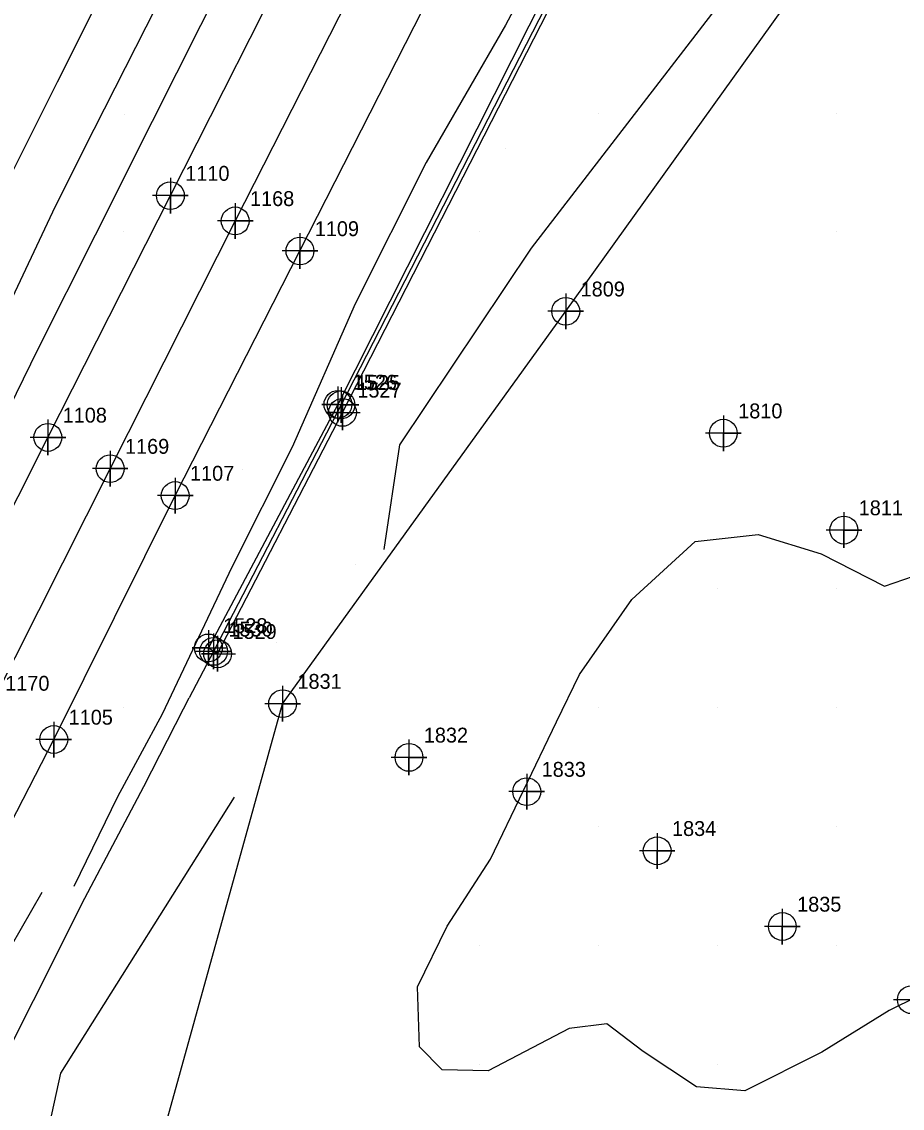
# Model space of a CAD drawing. Extents: x 2062781 to 2066835, y 358981 to 366501.
# Drawn here: x 2063838 to 2063986.2, y 360927.9 to 361110.7 of the extents above; entities that cross this region are included whole.
import ezdxf

# ---------------------------------------------------------------- set-up
doc = ezdxf.new("R2010")
doc.units = 0
for name, color, linetype in [('Exist DTM Breakline', 7, 'Continuous'), ('Exist DTM Breakline Cogo Number', 7, 'Continuous'), ('Exist DTM Breakline Cogo Point CELL', 7, 'Continuous'), ('Exist DTM Crownline', 7, 'Continuous'), ('Exist DTM Crownline Cogo Number', 7, 'Continuous'), ('Exist DTM Crownline Cogo Point CELL', 7, 'Continuous'), ('Exist DTM Regular Point CELL', 7, 'Continuous'), ('Exist DTM Regular Point Cogo Number', 7, 'Continuous'), ('Exist DTM Ridgeline', 7, 'Continuous'), ('Exist DTM Ridgeline Cogo Number', 7, 'Continuous'), ('Exist DTM Ridgeline Cogo Point CELL', 7, 'Continuous'), ('Exist Roads Curbs', 7, 'Continuous'), ('Exist Roads Curbs Cogo Number', 7, 'Continuous'), ('Exist Roads Curbs Cogo Point CELL', 7, 'Continuous'), ('Exist Roads EOP', 7, 'Continuous'), ('Exist Roads EOP Cogo Number', 7, 'Continuous'), ('Exist Roads EOP Cogo Point CELL', 7, 'Continuous'), ('PH Exist DTM Breakline', 7, 'Continuous'), ('PH Exist DTM Point', 7, 'Continuous')]:
    doc.layers.add(name, color=color, linetype=linetype)

msp = doc.modelspace()

# ---------------------------------------------------------------- linework, layer by layer
at = {"layer": 'Exist DTM Breakline'}
msp.add_line((2063870.34, 361004.8), (2063866.24, 360996.99), dxfattribs=at)
msp.add_lwpolyline([(2064057.56, 361350.08), (2064041.78, 361331.46), (2064030.47, 361314.75), (2064022.01, 361300.66), (2063997.63, 361253.31), (2063965.85, 361191.78), (2063927.22, 361115.25), (2063891.78, 361046.28), (2063870.34, 361004.8)], dxfattribs=at)
at = {"layer": 'Exist DTM Breakline Cogo Point CELL'}
for points in [[(2063891.78, 361049.28), (2063891.78, 361043.28), (2063891.78, 361046.28), (2063894.78, 361046.28), (2063888.78, 361046.28)], [(2063891.78, 361049.28), (2063891.78, 361043.28), (2063891.78, 361046.28), (2063894.78, 361046.28), (2063888.78, 361046.28)], [(2063891.78, 361049.28), (2063891.78, 361043.28), (2063891.78, 361046.28), (2063894.78, 361046.28), (2063888.78, 361046.28)], [(2063870.34, 361007.8), (2063870.34, 361001.8), (2063870.34, 361004.8), (2063873.34, 361004.8), (2063867.34, 361004.8)], [(2063870.34, 361007.8), (2063870.34, 361001.8), (2063870.34, 361004.8), (2063873.34, 361004.8), (2063867.34, 361004.8)], [(2063870.34, 361007.8), (2063870.34, 361001.8), (2063870.34, 361004.8), (2063873.34, 361004.8), (2063867.34, 361004.8)]]:
    msp.add_lwpolyline(points, dxfattribs=at)
for centre in [(2063891.78, 361046.28), (2063891.78, 361046.28), (2063891.78, 361046.28), (2063870.34, 361004.8), (2063870.34, 361004.8), (2063870.34, 361004.8)]:
    msp.add_circle(centre, 2.34, dxfattribs=at)
at = {"layer": 'Exist DTM Crownline'}
msp.add_lwpolyline([(2064265.44, 361845.69), (2064239.97, 361795.64), (2064213.32, 361743.86), (2064188.56, 361695.08), (2064163.47, 361645.6), (2064134.87, 361589.21), (2064123.65, 361567.03), (2064102.77, 361525.75), (2064081.5, 361483.76), (2064060.49, 361443.22), (2064039.79, 361402.12), (2064017.95, 361359.29), (2063998.02, 361320.11), (2063977.86, 361280.75), (2063957.66, 361241.43), (2063938.49, 361203.85), (2063917.61, 361163.02), (2063896.2, 361120.91), (2063873.97, 361077.23), (2063852.93, 361035.55), (2063832.77, 360995.69), (2063813.38, 360956.99), (2063791.84, 360915.2), (2063771.3, 360874.47)], dxfattribs=at)
at = {"layer": 'Exist DTM Crownline Cogo Point CELL'}
for points in [[(2063873.97, 361080.23), (2063873.97, 361074.23), (2063873.97, 361077.23), (2063876.97, 361077.23), (2063870.97, 361077.23)], [(2063873.97, 361080.23), (2063873.97, 361074.23), (2063873.97, 361077.23), (2063876.97, 361077.23), (2063870.97, 361077.23)], [(2063873.97, 361080.23), (2063873.97, 361074.23), (2063873.97, 361077.23), (2063876.97, 361077.23), (2063870.97, 361077.23)], [(2063852.93, 361038.55), (2063852.93, 361032.55), (2063852.93, 361035.55), (2063855.93, 361035.55), (2063849.93, 361035.55)], [(2063852.93, 361038.55), (2063852.93, 361032.55), (2063852.93, 361035.55), (2063855.93, 361035.55), (2063849.93, 361035.55)], [(2063852.93, 361038.55), (2063852.93, 361032.55), (2063852.93, 361035.55), (2063855.93, 361035.55), (2063849.93, 361035.55)]]:
    msp.add_lwpolyline(points, dxfattribs=at)
for centre in [(2063873.97, 361077.23), (2063873.97, 361077.23), (2063873.97, 361077.23), (2063852.93, 361035.55), (2063852.93, 361035.55), (2063852.93, 361035.55)]:
    msp.add_circle(centre, 2.34, dxfattribs=at)
at = {"layer": 'Exist DTM Regular Point CELL'}
for points in [[(2063956.13, 361044.51), (2063956.13, 361038.51), (2063956.13, 361041.51), (2063959.13, 361041.51), (2063953.13, 361041.51)], [(2063976.41, 361028.21), (2063976.41, 361022.21), (2063976.41, 361025.21), (2063979.41, 361025.21), (2063973.41, 361025.21)], [(2063903.22, 360989.97), (2063903.22, 360983.97), (2063903.22, 360986.97), (2063906.22, 360986.97), (2063900.22, 360986.97)], [(2063923.05, 360984.21), (2063923.05, 360978.21), (2063923.05, 360981.21), (2063926.05, 360981.21), (2063920.05, 360981.21)], [(2063944.99, 360974.25), (2063944.99, 360968.25), (2063944.99, 360971.25), (2063947.99, 360971.25), (2063941.99, 360971.25)], [(2063966.05, 360961.52), (2063966.05, 360955.52), (2063966.05, 360958.52), (2063969.05, 360958.52), (2063963.05, 360958.52)], [(2063987.78, 360949.2), (2063987.78, 360943.2), (2063987.78, 360946.2), (2063990.78, 360946.2), (2063984.78, 360946.2)]]:
    msp.add_lwpolyline(points, dxfattribs=at)
for centre in [(2063956.13, 361041.51), (2063976.41, 361025.21), (2063903.22, 360986.97), (2063923.05, 360981.21), (2063944.99, 360971.25), (2063966.05, 360958.52), (2063987.78, 360946.2)]:
    msp.add_circle(centre, 2.34, dxfattribs=at)
at = {"layer": 'Exist DTM Ridgeline'}
msp.add_lwpolyline([(2063854.81, 360898.33), (2063881.95, 360996.01), (2063929.61, 361062.02), (2063994.22, 361152.11), (2064040.95, 361302.72)], dxfattribs=at)
at = {"layer": 'Exist DTM Ridgeline Cogo Point CELL'}
for points in [[(2063929.61, 361065.02), (2063929.61, 361059.02), (2063929.61, 361062.02), (2063932.61, 361062.02), (2063926.61, 361062.02)], [(2063929.61, 361065.02), (2063929.61, 361059.02), (2063929.61, 361062.02), (2063932.61, 361062.02), (2063926.61, 361062.02)], [(2063929.61, 361065.02), (2063929.61, 361059.02), (2063929.61, 361062.02), (2063932.61, 361062.02), (2063926.61, 361062.02)], [(2063881.95, 360999.01), (2063881.95, 360993.01), (2063881.95, 360996.01), (2063884.95, 360996.01), (2063878.95, 360996.01)], [(2063881.95, 360999.01), (2063881.95, 360993.01), (2063881.95, 360996.01), (2063884.95, 360996.01), (2063878.95, 360996.01)], [(2063881.95, 360999.01), (2063881.95, 360993.01), (2063881.95, 360996.01), (2063884.95, 360996.01), (2063878.95, 360996.01)]]:
    msp.add_lwpolyline(points, dxfattribs=at)
for centre in [(2063929.61, 361062.02), (2063929.61, 361062.02), (2063929.61, 361062.02), (2063881.95, 360996.01), (2063881.95, 360996.01), (2063881.95, 360996.01)]:
    msp.add_circle(centre, 2.34, dxfattribs=at)
at = {"layer": 'Exist Roads Curbs'}
for points in [[(2064056.86, 361351.14), (2064040.98, 361332.19), (2064029.8, 361315.76), (2064021.05, 361301.02), (2063996.57, 361253.68), (2063965.22, 361192.21), (2063926.31, 361115.84), (2063891.26, 361046.35), (2063869.46, 361005.39)], [(2063871.01, 361004.4), (2063892.03, 361045.01), (2063927.85, 361114.94), (2063967.15, 361191.97), (2063998.41, 361252.65), (2064022.95, 361300.07), (2064031.32, 361314), (2064042.62, 361330.84), (2064058.37, 361349.48)], [(2063871.01, 361004.4), (2063870.34, 361004.8), (2063869.46, 361005.39)]]:
    msp.add_lwpolyline(points, dxfattribs=at)
at = {"layer": 'Exist Roads Curbs Cogo Point CELL'}
for points in [[(2063891.26, 361049.35), (2063891.26, 361043.35), (2063891.26, 361046.35), (2063888.53, 361046.35), (2063894.26, 361046.35)], [(2063891.26, 361049.35), (2063891.26, 361043.35), (2063891.26, 361046.35), (2063888.53, 361046.35), (2063894.26, 361046.35)], [(2063891.26, 361049.35), (2063891.26, 361043.35), (2063891.26, 361046.35), (2063888.53, 361046.35), (2063894.26, 361046.35)], [(2063892.03, 361048.01), (2063892.03, 361042.01), (2063892.03, 361045.01), (2063889.3, 361045.01), (2063895.03, 361045.01)], [(2063892.03, 361048.01), (2063892.03, 361042.01), (2063892.03, 361045.01), (2063889.3, 361045.01), (2063895.03, 361045.01)], [(2063892.03, 361048.01), (2063892.03, 361042.01), (2063892.03, 361045.01), (2063889.3, 361045.01), (2063895.03, 361045.01)], [(2063869.46, 361008.39), (2063869.46, 361002.39), (2063869.46, 361005.39), (2063866.73, 361005.39), (2063872.46, 361005.39)], [(2063869.46, 361008.39), (2063869.46, 361002.39), (2063869.46, 361005.39), (2063866.73, 361005.39), (2063872.46, 361005.39)], [(2063869.46, 361008.39), (2063869.46, 361002.39), (2063869.46, 361005.39), (2063866.73, 361005.39), (2063872.46, 361005.39)], [(2063871.01, 361007.4), (2063871.01, 361001.4), (2063871.01, 361004.4), (2063868.28, 361004.4), (2063874.01, 361004.4)], [(2063871.01, 361007.4), (2063871.01, 361001.4), (2063871.01, 361004.4), (2063868.28, 361004.4), (2063874.01, 361004.4)], [(2063871.01, 361007.4), (2063871.01, 361001.4), (2063871.01, 361004.4), (2063868.28, 361004.4), (2063874.01, 361004.4)]]:
    msp.add_lwpolyline(points, dxfattribs=at)
for centre in [(2063891.26, 361046.35), (2063891.26, 361046.35), (2063891.26, 361046.35), (2063892.03, 361045.01), (2063892.03, 361045.01), (2063892.03, 361045.01), (2063869.46, 361005.39), (2063869.46, 361005.39), (2063869.46, 361005.39), (2063871.01, 361004.4), (2063871.01, 361004.4), (2063871.01, 361004.4)]:
    msp.add_circle(centre, 2.34, dxfattribs=at)
at = {"layer": 'Exist Roads EOP'}
for points in [[(2063761.09, 360880.78), (2063780.86, 360919.69), (2063802.57, 360962.16), (2063822.37, 361000.99), (2063842.44, 361040.8), (2063863.07, 361081.48), (2063885.45, 361125.76), (2063907.42, 361168.78), (2063928.26, 361209.85), (2063947.54, 361247.66), (2063967.28, 361286.12)], [(2063782.17, 360869.73), (2063802.66, 360909.81), (2063823.78, 360951.78), (2063843.44, 360989.98), (2063863.87, 361031.02), (2063884.87, 361072.17), (2063907.05, 361115.85), (2063928.7, 361158.45), (2063949.22, 361198.71), (2063968.74, 361236.86), (2063988.59, 361275.84)]]:
    msp.add_lwpolyline(points, dxfattribs=at)
at = {"layer": 'Exist Roads EOP Cogo Point CELL'}
for points in [[(2063863.07, 361084.48), (2063863.07, 361078.48), (2063863.07, 361081.48), (2063866.07, 361081.48), (2063860.07, 361081.48)], [(2063863.07, 361084.48), (2063863.07, 361078.48), (2063863.07, 361081.48), (2063866.07, 361081.48), (2063860.07, 361081.48)], [(2063863.07, 361084.48), (2063863.07, 361078.48), (2063863.07, 361081.48), (2063866.07, 361081.48), (2063860.07, 361081.48)], [(2063884.87, 361075.17), (2063884.87, 361069.17), (2063884.87, 361072.17), (2063887.87, 361072.17), (2063881.87, 361072.17)], [(2063884.87, 361075.17), (2063884.87, 361069.17), (2063884.87, 361072.17), (2063887.87, 361072.17), (2063881.87, 361072.17)], [(2063884.87, 361075.17), (2063884.87, 361069.17), (2063884.87, 361072.17), (2063887.87, 361072.17), (2063881.87, 361072.17)], [(2063842.44, 361043.8), (2063842.44, 361037.8), (2063842.44, 361040.8), (2063845.44, 361040.8), (2063839.44, 361040.8)], [(2063842.44, 361043.8), (2063842.44, 361037.8), (2063842.44, 361040.8), (2063845.44, 361040.8), (2063839.44, 361040.8)], [(2063842.44, 361043.8), (2063842.44, 361037.8), (2063842.44, 361040.8), (2063845.44, 361040.8), (2063839.44, 361040.8)], [(2063863.87, 361034.02), (2063863.87, 361028.02), (2063863.87, 361031.02), (2063866.87, 361031.02), (2063860.87, 361031.02)], [(2063863.87, 361034.02), (2063863.87, 361028.02), (2063863.87, 361031.02), (2063866.87, 361031.02), (2063860.87, 361031.02)], [(2063863.87, 361034.02), (2063863.87, 361028.02), (2063863.87, 361031.02), (2063866.87, 361031.02), (2063860.87, 361031.02)], [(2063843.44, 360992.98), (2063843.44, 360986.98), (2063843.44, 360989.98), (2063846.44, 360989.98), (2063840.44, 360989.98)], [(2063843.44, 360992.98), (2063843.44, 360986.98), (2063843.44, 360989.98), (2063846.44, 360989.98), (2063840.44, 360989.98)], [(2063843.44, 360992.98), (2063843.44, 360986.98), (2063843.44, 360989.98), (2063846.44, 360989.98), (2063840.44, 360989.98)]]:
    msp.add_lwpolyline(points, dxfattribs=at)
for centre in [(2063863.07, 361081.48), (2063863.07, 361081.48), (2063863.07, 361081.48), (2063884.87, 361072.17), (2063884.87, 361072.17), (2063884.87, 361072.17), (2063842.44, 361040.8), (2063842.44, 361040.8), (2063842.44, 361040.8), (2063863.87, 361031.02), (2063863.87, 361031.02), (2063863.87, 361031.02), (2063843.44, 360989.98), (2063843.44, 360989.98), (2063843.44, 360989.98)]:
    msp.add_circle(centre, 2.34, dxfattribs=at)
at = {"layer": 'PH Exist DTM Breakline'}
for points in [[(2063899.03, 361021.92), (2063901.66, 361039.56), (2063923.83, 361072.66), (2063956.8, 361115.48), (2063977.59, 361161.23), (2063989.54, 361195.71), (2064007.38, 361228.78), (2064015.81, 361274.95), (2064037.38, 361312.02), (2064055.44, 361337.27), (2064056.38, 361338.79)], [(2063776.97, 360931.53), (2063786.31, 360949.96), (2063796.45, 360970.24), (2063808.51, 360993.12), (2063819.12, 361014.33), (2063831.1, 361035.97), (2063840.78, 361055.58), (2063850.48, 361074.91), (2063860.06, 361094), (2063872.29, 361118.37), (2063882.18, 361138.07), (2063892.59, 361158.8), (2063902.95, 361178.15), (2063912.46, 361197.11), (2063922.39, 361217.06), (2063931.47, 361235.97), (2063939.95, 361252.86), (2063951.79, 361276.55)], [(2064001.07, 361274.07), (2063992.61, 361254.48), (2063986.72, 361242.76), (2063981.77, 361232.89), (2063968.86, 361208.92), (2063960.66, 361190.77), (2063951.19, 361172.03), (2063947.31, 361164.29), (2063938.42, 361146.57), (2063930.81, 361131.41), (2063919.44, 361110.17), (2063906.11, 361087.07), (2063894.15, 361063.25), (2063883.54, 361039.15), (2063873.4, 361018.96), (2063861.67, 360994.23), (2063854.16, 360980.32), (2063846.84, 360965.25)], [(2063940.31, 361271.89), (2063929.57, 361250.03), (2063913.38, 361217.97), (2063901.36, 361193.15), (2063883.16, 361157.8), (2063873.69, 361140.09), (2063862.48, 361116.85), (2063850.2, 361092.63), (2063843.69, 361079.66), (2063835.08, 361061.43), (2063825.06, 361041.44), (2063810.6, 361012.44), (2063797.39, 360986.7), (2063784.2, 360962.66), (2063769.13, 360934.13)], [(2063927.87, 361268.4), (2063920.91, 361255.93), (2063911.68, 361237.56), (2063903.44, 361218.5), (2063890.79, 361193.3), (2063879.01, 361169.84), (2063863.75, 361139.42), (2063856.71, 361125.9), (2063844, 361100.58), (2063827.45, 361067.61), (2063813.7, 361040.21), (2063801.2, 361015.31), (2063788.42, 360989.38), (2063775.98, 360964.6), (2063761.4, 360935.63)], [(2063993.37, 360948.98), (2063984.02, 360944.39), (2063972.69, 360937.37), (2063959.73, 360930.86), (2063951.6, 360931.56), (2063942.66, 360937.47), (2063936.51, 360942.14), (2063930.18, 360941.34), (2063916.55, 360934.25), (2063908.78, 360934.38), (2063905, 360938.25), (2063904.67, 360948.39), (2063909.67, 360958.57), (2063916.94, 360969.84), (2063928.07, 360992.97), (2063931.9, 361000.92), (2063940.72, 361013.51), (2063951.37, 361023.27), (2063961.96, 361024.46), (2063972.61, 361021.22), (2063983.23, 361015.78), (2063988.14, 361017.45)], [(2063819.62, 360906.07), (2063829.22, 360924.6), (2063840, 360946.07), (2063848.65, 360963.3), (2063858.59, 360982.09), (2063865.26, 360995.13), (2063866.24, 360996.99)], [(2063835.3, 360891.27), (2063844.62, 360933.82), (2063873.88, 360980.28)], [(2063810.81, 360907.56), (2063820.79, 360925.62), (2063831, 360946.1), (2063841.5, 360964.29)]]:
    msp.add_lwpolyline(points, dxfattribs=at)
at = {"layer": 'PH Exist DTM Point'}
for p, q in [((2063855.33, 361095.1), (2063855.33, 361095.1)), ((2063935.13, 361095.38), (2063935.13, 361095.38)), ((2063975.13, 361095.38), (2063975.13, 361095.38)), ((2063919.41, 361089.49), (2063919.41, 361089.49)), ((2063855.11, 361075.4), (2063855.11, 361075.4)), ((2063894.62, 361075.93), (2063894.62, 361075.93)), ((2063915.13, 361075.38), (2063915.13, 361075.38)), ((2063975.13, 361075.38), (2063975.13, 361075.38)), ((2063875.13, 361035.38), (2063875.13, 361035.38)), ((2063894.14, 361019.42), (2063894.14, 361019.42)), ((2063955.13, 361015.38), (2063955.13, 361015.38)), ((2063975.13, 361015.38), (2063975.13, 361015.38)), ((2063880.85, 361006.3), (2063880.85, 361006.3)), ((2063855.13, 360995.38), (2063855.13, 360995.38)), ((2063935.13, 360995.38), (2063935.13, 360995.38)), ((2063955.13, 360995.38), (2063955.13, 360995.38)), ((2063975.13, 360995.38), (2063975.13, 360995.38)), ((2063935.13, 360975.38), (2063935.13, 360975.38)), ((2063955.13, 360975.38), (2063955.13, 360975.38)), ((2063975.13, 360975.38), (2063975.13, 360975.38)), ((2063915.13, 360955.38), (2063915.13, 360955.38)), ((2063935.13, 360955.38), (2063935.13, 360955.38)), ((2063955.13, 360955.38), (2063955.13, 360955.38)), ((2063975.13, 360955.38), (2063975.13, 360955.38)), ((2063915.13, 360935.38), (2063915.13, 360935.38)), ((2063955.13, 360935.38), (2063955.13, 360935.38))]:
    msp.add_line(p, q, dxfattribs=at)

# ---------------------------------------------------------------- texts
at = {"layer": 'Exist DTM Breakline Cogo Number'}
for s, p in [('1525', (2063894.28, 361048.78)), ('1525', (2063894.28, 361048.78)), ('1525', (2063894.28, 361048.78)), ('1530', (2063872.84, 361007.3)), ('1530', (2063872.84, 361007.3)), ('1530', (2063872.84, 361007.3))]:
    msp.add_text(s, height=2.5, dxfattribs=at).set_placement(p)
at = {"layer": 'Exist DTM Crownline Cogo Number'}
for s, p in [('1168', (2063876.47, 361079.73)), ('1168', (2063876.47, 361079.73)), ('1168', (2063876.47, 361079.73)), ('1169', (2063855.43, 361038.05)), ('1169', (2063855.43, 361038.05)), ('1169', (2063855.43, 361038.05)), ('1170', (2063835.27, 360998.19)), ('1170', (2063835.27, 360998.19)), ('1170', (2063835.27, 360998.19))]:
    msp.add_text(s, height=2.5, dxfattribs=at).set_placement(p)
at = {"layer": 'Exist DTM Regular Point Cogo Number'}
for s, p in [('1810', (2063958.63, 361044.01)), ('1810', (2063958.63, 361044.01)), ('1810', (2063958.63, 361044.01)), ('1811', (2063978.91, 361027.71)), ('1811', (2063978.91, 361027.71)), ('1811', (2063978.91, 361027.71)), ('1832', (2063905.72, 360989.47)), ('1832', (2063905.72, 360989.47)), ('1832', (2063905.72, 360989.47)), ('1833', (2063925.55, 360983.71)), ('1833', (2063925.55, 360983.71)), ('1833', (2063925.55, 360983.71)), ('1834', (2063947.49, 360973.75)), ('1834', (2063947.49, 360973.75)), ('1834', (2063947.49, 360973.75)), ('1835', (2063968.55, 360961.02)), ('1835', (2063968.55, 360961.02)), ('1835', (2063968.55, 360961.02))]:
    msp.add_text(s, height=2.5, dxfattribs=at).set_placement(p)
at = {"layer": 'Exist DTM Ridgeline Cogo Number'}
for s, p in [('1809', (2063932.11, 361064.52)), ('1809', (2063932.11, 361064.52)), ('1809', (2063932.11, 361064.52)), ('1831', (2063884.45, 360998.51)), ('1831', (2063884.45, 360998.51)), ('1831', (2063884.45, 360998.51))]:
    msp.add_text(s, height=2.5, dxfattribs=at).set_placement(p)
at = {"layer": 'Exist Roads Curbs Cogo Number'}
for s, p in [('1526', (2063893.76, 361048.85)), ('1526', (2063893.76, 361048.85)), ('1526', (2063893.76, 361048.85)), ('1527', (2063894.53, 361047.51)), ('1527', (2063894.53, 361047.51)), ('1527', (2063894.53, 361047.51)), ('1528', (2063871.96, 361007.89)), ('1528', (2063871.96, 361007.89)), ('1528', (2063871.96, 361007.89)), ('1529', (2063873.51, 361006.9)), ('1529', (2063873.51, 361006.9)), ('1529', (2063873.51, 361006.9))]:
    msp.add_text(s, height=2.5, dxfattribs=at).set_placement(p)
at = {"layer": 'Exist Roads EOP Cogo Number'}
for s, p in [('1110', (2063865.57, 361083.98)), ('1110', (2063865.57, 361083.98)), ('1110', (2063865.57, 361083.98)), ('1109', (2063887.37, 361074.67)), ('1109', (2063887.37, 361074.67)), ('1109', (2063887.37, 361074.67)), ('1108', (2063844.94, 361043.3)), ('1108', (2063844.94, 361043.3)), ('1108', (2063844.94, 361043.3)), ('1107', (2063866.37, 361033.52)), ('1107', (2063866.37, 361033.52)), ('1107', (2063866.37, 361033.52)), ('1105', (2063845.94, 360992.48)), ('1105', (2063845.94, 360992.48)), ('1105', (2063845.94, 360992.48))]:
    msp.add_text(s, height=2.5, dxfattribs=at).set_placement(p)

doc.saveas('drawing.dxf')
